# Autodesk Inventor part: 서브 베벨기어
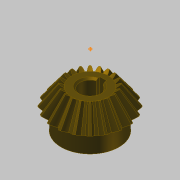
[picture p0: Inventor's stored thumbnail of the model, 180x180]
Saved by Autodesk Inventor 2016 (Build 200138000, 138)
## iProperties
Created: 2014-10
Part Number: 서브 베벨기어
Material: 강철, 탄소
Document SubType Name: Modeling
Designer: KYOUNG IL JANG
Categories: <?xml version="1.0" encoding="UTF-16"?> <MemberInstance><Categories><FamilyTemplate><FamilyTemplateParameter ValueType="xs:double" Id="1" ObjectReferenceKey="da
Mass: 134.866 g
Surface Area: 63.6518 cm^2
Volume: 17.1585 cm^3
Density: 7.86 g/cm^3
Appearance: 얼룩무늬
CustomPartVersion: 1
Revision Number: 1
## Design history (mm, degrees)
node "맨 위 점"
node "메쉬 평면2"
sketch "톱니 본체 스케치"
  geometry: L1 (0, 0)-(18.003, -31.331); L2 (18.003, -31.331)-(21.664, -28.891); L3 (21.664, -28.891)-(0, 0); L4 (20, -30)-(0, 0); L5 (10.813, -18.818)-(13.012, -17.352); L6 (18.003, -31.331)-(10.813, -18.818); L7 (21.664, -28.891)-(13.012, -17.352); L8 (0, -39.387)-(0, 6.564) reference; L9 (0, -30)-(21.664, -30)
  constraints: 16 end point, 4 point on line, 3 perpendicular, 2 collinear, 1 horizontal alignment, 1 vertical alignment
  dimensions: "d0" = 40 diameter of L4.start L8 (= da_de); "d1" = 36.00616 diameter of L1.end L8 (= da_dfe); "d2" = 43.3282 diameter of L2.end L8 (= da_dae); "d3" = 14.4 distance between parallel lines of L2 L5 (= da_b); "d4" = 28.8906 vertical distance of L2.end L1.start (= da_ve)
revolve "톱니 본체" sketch "톱니 본체 스케치" stored, may be unused: angle "d5" = 90 deg
node "시작점"
node "톱니 평면"
sketch "시작 스케치"
  geometry: L1 (0, -23.505)-(0, 10.645) reference; L2 (-0.834, -2.928)-(0.834, -2.928); A1 r 8.898 centre (-9.698, -3.713) between (-0.834, -2.928) and (-3.903, 3.04); A2 r 8.898 centre (9.698, -3.713) between (3.903, 3.04) and (0.834, -2.928); A3 r 27.357 centre (0, -24.037) between (3.903, 3.04) and (-3.903, 3.04); 1 further point
  constraints: 6 point on circle, 3 centre point, 3 symmetric about line, 2 end point, 1 coincident, 1 perpendicular, 1 other
  dimensions: "d7" = 8.89846 radius of A1 (= fd_rr); "d8" = 9.69794 horizontal distance of point (0, -24.037) A1.centre (= fd_x); "d9" = 20.32439 vertical distance of point (0, -24.037) A1.centre (= fd_y); "d57" = 27.35701 radius of A3 (= 0.5 x fd_dva + 0.3 x da_he); "d58" = 21.10901 distance from line of A3.centre L2 (= 0.5 x fd_dva - 1.12 x da_he)
node "끝점"
  node "끝 평면"
sketch "3D 스케치 오른쪽"
  node "Helical Curve Right" dims "d65" = 229.90621 (computed from da_dm, da_delta, da_beta), "d66" = 31.5, "d67" = 40 (= da_de), "d68" = -5.88003 (= -da_delta), "d69" = 12.16458 (computed from fd_loft, da_delta)
node "끝 평면 오른쪽"
sketch "끝 스케치 오른쪽"
  geometry: L1 (0, -22.649)-(0, 12.15) reference; L2 (-0.497, -1.72)-(0.497, -1.72); A1 r 5.299 centre (-5.775, -2.187) between (-0.497, -1.72) and (-2.324, 1.834); A2 r 5.299 centre (5.775, -2.187) between (2.324, 1.834) and (0.497, -1.72); A3 r 16.291 centre (0, -14.29) between (2.324, 1.834) and (-2.324, 1.834); 1 further point
  constraints: 6 point on circle, 3 centre point, 3 symmetric about line, 2 end point, 1 coincident, 1 perpendicular, 1 other
  dimensions: "d70" = 5.77526 horizontal distance of A3.centre A1.centre (computed from fd_x, fd_ratio); "d71" = 12.10346 vertical distance of point (0, -14.29) A1.centre (computed from fd_y, fd_ratio); "d72" = 5.29916 radius of A1 (computed from fd_rr, fd_ratio); "d73" = 12.57071 distance from line of point (0, -14.29) L2 (computed from d58, fd_ratio); "d74" = 16.29149 radius of A3 (computed from d57, fd_ratio)
feature "로프트 오른쪽" sketch "끝 스케치 오른쪽" dims "d75" = 0, "d77" = 0, "d79" = 0, "d80" = 90 deg, "d85" = 20, "d92" = 90 deg, "d93" = 90 deg, "da_teethtype" = 0 [user parameter]
sketch "3D 스케치 왼쪽"
  node "Helical Curve Left" dims "d26" = 229.90621 (computed from da_dm, da_delta, da_beta), "d27" = 12.16458 (computed from fd_loft, da_delta), "d28" = 40 (= da_de), "d29" = -5.88003 (= -da_delta)
node "끝 평면 왼쪽"
sketch "끝 스케치 왼쪽" dims "d56" = 10.82768 (derived)
  geometry: L1 (0, -35.087)-(0, 18.089) reference; L2 (-0.497, -1.716)-(0.497, -1.716); A1 r 5.299 centre (-5.775, -2.183) between (-0.497, -1.716) and (-2.324, 1.838); A2 r 5.299 centre (5.775, -2.183) between (2.324, 1.838) and (0.497, -1.716); A3 r 16.291 centre (0, -14.287) between (2.324, 1.838) and (-2.324, 1.838); 2 further points; 1 other entity
  constraints: 6 point on circle, 3 centre point, 3 symmetric about line, 2 end point, 1 coincident, 2 other
  dimensions: "d30" = 5.29916 radius of A1 (computed from fd_rr, fd_ratio); "d31" = 5.77526 horizontal distance of point (0, -14.287) A1.centre (computed from fd_x, fd_ratio); "d32" = 12.10346 vertical distance of A1.centre point (0, -14.287) (computed from fd_y, fd_ratio); "d61" = 16.29149 radius of A3 (computed from d57, fd_ratio); "d62" = 12.57071 distance from line of point (0, -14.287) L2 (computed from d58, fd_ratio)
feature "로프트 왼쪽" sketch "끝 스케치 왼쪽" dims "d35" = 0, "d37" = 0, "d39" = 0, "d40" = 90 deg, "d84" = 10, "d90" = 90 deg, "d91" = 90 deg, "da_teethtype" = 0 [user parameter]
sketch "본체 스케치"
  geometry: L1 (0, -35.038)-(0, -19.531) reference; L2 (18.003, -31.331)-(10.813, -18.818) reference; L3 (10.813, -18.818)-(0, -18.818); L4 (18.003, -31.331)-(0, -31.331)
  constraints: 4 end point, 2 perpendicular, 2 point on line
revolve "본체 고정" sketch "본체 스케치" stored, may be unused: angle "d46" = 90 deg
feature "피치 지름" dims angle "d47" = 90 deg
sketch "스케치8"
  geometry: C1 r 17 at (0, 0); 1 further point
  constraints: 1 centre point, 1 coincident
  dimensions: "d94" = 34 diameter of C1
extrude "돌출1" join sketch "스케치8" distance "d95" = 10; taper "d96" = 0 deg
sketch "스케치9"
  geometry: 1 further point
hole "구멍1" sketch "스케치9" at (0, 0) diameter "d97" = 12; stored, may be unused: countersink angle "d101" = 90 deg, drill point angle "d103" = 118 deg; dims "d98" = 6, "d99" = 4, "d100" = 2, "d102" = 8
sketch "스케치10"
  geometry: 1 further point
sketch "스케치11"
  geometry: 1 further point
sketch "스케치12"
  geometry: L1 (-2, 5.657)-(-2, 7.8); L2 (-2, 7.8)-(2, 7.8); L3 (2, 7.8)-(2, 5.657); A1 r 6 centre (0, 0) between (-2, 5.657) and (2, 5.657) reference; 1 further point
  constraints: 6 end point, 2 parallel, 2 point on circle, 1 perpendicular, 1 vertical
  dimensions: "d104" = 4 distance of L1.end L2.end; "d105" = 13.8 dimension on A1 L2
extrude "돌출2" cut sketch "스케치12" stored distance "d106" = 7; taper "d107" = 0 deg
chamfer "모따기1" distance "d108" = 1; stored, may be unused: second distance "d109" = 2, angle "d110" = 45 deg
body "Solid1"
feature "로프트" dims "d17" = 0, "d18" = 90 deg, "d19" = 0, "d20" = 90 deg, "d89" = 0, "da_teethtype" = 0 [user parameter]
pattern_circular "원형 패턴" dims angle "d22" = 360 deg, "d88" = 0, "da_teethtype" = 0 [user parameter]
pattern_circular "원형 패턴 오른쪽" dims angle "d82" = 360 deg, "da_teethtype" = 0 [user parameter]
pattern_circular "원형 패턴 왼쪽" dims angle "d42" = 360 deg, "da_teethtype" = 0 [user parameter]
sketch "끝 스케치"
  geometry: L1 (0, -15.359)-(0, 6.983) reference; L2 (-0.497, -1.72)-(0.497, -1.72); A1 r 5.299 centre (-5.775, -2.187) between (-0.497, -1.72) and (-2.324, 1.834); A2 r 5.299 centre (5.775, -2.187) between (2.324, 1.834) and (0.497, -1.72); A3 r 16.291 centre (0, -14.29) between (2.324, 1.834) and (-2.324, 1.834); 1 further point
  constraints: 6 point on circle, 3 centre point, 3 symmetric about line, 2 end point, 1 coincident, 1 other
  dimensions: "d12" = 5.29916 radius of A1 (computed from fd_rr, fd_ratio); "d15" = 5.77526 horizontal distance of A1.centre point (0, -14.29) (computed from fd_x, fd_ratio); "d16" = 12.10346 vertical distance of A1.centre point (0, -14.29) (computed from fd_y, fd_ratio); "d59" = 16.29149 radius of A3 (computed from d57, fd_ratio); "d60" = 12.57071 distance from line of A3.centre L2 (computed from d58, fd_ratio)
sketch "Sketch6"
  geometry: L1 (20, -30)-(0, 0) reference; L2 (0, -37.8)-(0, 6.3) reference
body "Srf1"
other parameters: "da_b" = 14.4 [user parameter; used in 2 equation terms], "da_de" = 40 [user parameter; used in 4 equation terms], "da_dae" = 43.3282 [user parameter; used in 2 equation terms], "da_dfe" = 36.00616 [user parameter; used in 1 equation term], "da_le" = 36.05551 [user parameter; used in 1 equation term], "da_omega" = 90 deg [user parameter; used in 1 equation term], "da_beta" = 0 [user parameter; used in 2 equation terms], "da_delta" = 5.88003 [user parameter; used in 8 equation terms], "da_alpha" = 20 deg [user parameter; used in 2 equation terms], "da_he" = 4.4 [user parameter; used in 4 equation terms], "da_ve" = 28.8906 [user parameter; used in 1 equation term], "fd_dv" = 48.07402 (computed from da_de, da_delta) [user parameter; used in 1 equation term], "fd_dva" = 52.07402 (computed from da_dae, da_delta) [user parameter; used in 3 equation terms], "fd_dvb" = 45.1748 (computed from fd_dv, da_alpha) [user parameter; used in 2 equation terms], "da_zv" = 240.37008 [user parameter; used in 1 equation term], "fd_loft" = 14.62 (= da_b + 0.05 x da_he) [user parameter; used in 4 equation terms], "fd_ratio" = 5.95514 (computed from da_le, fd_loft) [user parameter; used in 15 equation terms], "fd_rr" = 8.89846 (computed from fd_dd, fd_dvb) [user parameter; used in 6 equation terms], "fd_angle" = 0.66075 (computed from da_zv) [user parameter; used in 4 equation terms], "fd_x1" = 1.58709 (computed from da_dvw, fd_angle) [user parameter; used in 1 equation term], "fd_y1" = 23.98456 (computed from da_dvw, fd_angle) [user parameter; used in 1 equation term], "fd_x2" = 8.11084 (computed from fd_rr, fd_angle2, fd_angle) [user parameter; used in 1 equation term], "fd_y2" = 3.66016 (computed from fd_rr, fd_angle2, fd_angle) [user parameter; used in 1 equation term], "fd_x" = 9.69794 (= fd_x1 + fd_x2) [user parameter; used in 4 equation terms], "fd_y" = 20.32439 (= fd_y1 - fd_y2) [user parameter; used in 4 equation terms], "fd_angle2" = 3.57832 (computed from fd_dvb, fd_dd, da_alpha) [user parameter; used in 2 equation terms], "fd_dd" = 48.55402 (= fd_dva - 0.8 x da_he) [user parameter; used in 2 equation terms], "da_dvw" = 48.07402 [user parameter; used in 2 equation terms], "d11" = 14.62 (= fd_loft), "da_dm" = 32.01232 [user parameter; used in 2 equation terms], "da_x" = 0 [user parameter], "da_m" = 2 [user parameter], "d48" = 0, "d49" = 0, "d50" = 90 deg (= da_omega), "d51" = 9 deg (computed from da_z), "d52" = 0, "d53" = 0, "d54" = 0
